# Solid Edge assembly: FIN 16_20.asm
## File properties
Title: Zylinder
Author: bmolnar
Template: iso assembly.asm
Last saved by: bmolnar
Revision: 9
Application: Solid Edge
Username: bmolnar
Dokumentum tartalom típus: 1
Document Number: FIN 16/20
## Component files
Kolbenstange.par
Profilrohr.par
Kit_1.par
Kit_2.par
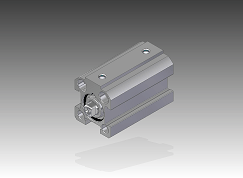
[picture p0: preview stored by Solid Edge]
